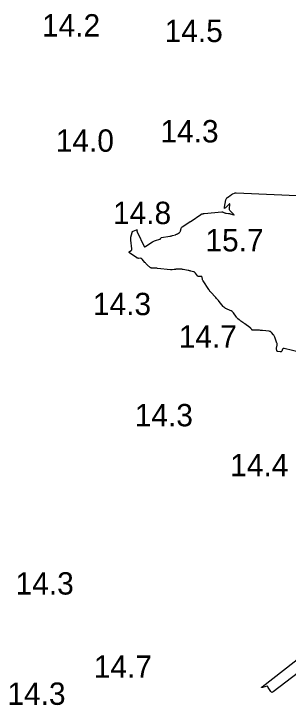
# Model space of a CAD drawing. Extents: x 1023796 to 1112670, y 656573 to 837340.
# Drawn here: x 1101279.7 to 1101341.1, y 687887.6 to 688042.2 of the extents above; entities that cross this region are included whole.
import ezdxf

# ---------------------------------------------------------------- set-up
doc = ezdxf.new("R2010")
doc.units = 0
doc.layers.add('V-CHAN-CONT-15FT', color=7, linetype='Continuous')
doc.layers.add('V-TOPO-SOUN', color=7, linetype='Continuous')

msp = doc.modelspace()

# ---------------------------------------------------------------- linework, layer by layer
at = {"layer": 'V-CHAN-CONT-15FT'}
for points in [[(1101345.78, 687966.02), (1101340.14, 687967.39), (1101340.04, 687967.4), (1101339.95, 687967.38), (1101339.87, 687967.32), (1101339.82, 687967.23), (1101339.62, 687966.81), (1101339.56, 687966.72), (1101339.49, 687966.66), (1101339.4, 687966.63), (1101339.29, 687966.62), (1101338.74, 687966.67), (1101338.65, 687966.69), (1101338.58, 687966.74), (1101338.54, 687966.81), (1101338.52, 687966.9), (1101338.48, 687967.31), (1101338.48, 687967.42), (1101338.48, 687967.52), (1101338.49, 687967.62), (1101338.5, 687967.73), (1101338.58, 687968.15), (1101338.59, 687968.26), (1101338.59, 687968.36), (1101338.57, 687968.47), (1101338.54, 687968.57), (1101338.08, 687969.9), (1101338.02, 687970.04), (1101337.94, 687970.19), (1101337.86, 687970.32), (1101337.76, 687970.45), (1101337.35, 687970.94), (1101337.24, 687971.06), (1101337.11, 687971.14), (1101336.97, 687971.2), (1101336.82, 687971.23), (1101335.35, 687971.39), (1101335.12, 687971.41), (1101334.89, 687971.43), (1101334.65, 687971.44), (1101334.42, 687971.45), (1101333.17, 687971.46), (1101333.1, 687971.47), (1101333.03, 687971.5), (1101332.97, 687971.54), (1101332.92, 687971.59), (1101332.73, 687971.86), (1101332.69, 687971.92), (1101332.63, 687971.98), (1101332.57, 687972.03), (1101332.51, 687972.08), (1101331.39, 687972.86), (1101331.28, 687972.94), (1101331.17, 687973.01), (1101331.06, 687973.09), (1101330.96, 687973.16), (1101330.49, 687973.48), (1101330.4, 687973.54), (1101330.31, 687973.61), (1101330.22, 687973.68), (1101330.14, 687973.75), (1101329.8, 687974.04), (1101329.72, 687974.11), (1101329.65, 687974.19), (1101329.57, 687974.28), (1101329.51, 687974.37), (1101328.83, 687975.32), (1101328.69, 687975.49), (1101328.52, 687975.65), (1101328.34, 687975.77), (1101328.13, 687975.87), (1101327.27, 687976.23), (1101327.06, 687976.33), (1101326.87, 687976.45), (1101326.7, 687976.6), (1101326.55, 687976.77), (1101325.66, 687977.87), (1101325.47, 687978.1), (1101325.27, 687978.32), (1101325.07, 687978.54), (1101324.87, 687978.76), (1101323.68, 687980.03), (1101323.66, 687980.05), (1101323.65, 687980.07), (1101323.64, 687980.09), (1101323.63, 687980.11), (1101323.58, 687980.21), (1101323.57, 687980.22), (1101323.57, 687980.23), (1101323.56, 687980.24), (1101323.55, 687980.25), (1101323.52, 687980.28), (1101323.51, 687980.29), (1101323.5, 687980.3), (1101323.49, 687980.31), (1101323.49, 687980.32), (1101323.38, 687980.48), (1101323.36, 687980.51), (1101323.34, 687980.54), (1101323.32, 687980.56), (1101323.3, 687980.59), (1101322.03, 687982.52), (1101321.98, 687982.61), (1101321.94, 687982.7), (1101321.91, 687982.79), (1101321.9, 687982.88), (1101321.86, 687983.27), (1101321.83, 687983.36), (1101321.79, 687983.42), (1101321.73, 687983.46), (1101321.64, 687983.47), (1101321.16, 687983.47), (1101321.06, 687983.48), (1101320.96, 687983.51), (1101320.88, 687983.56), (1101320.8, 687983.64), (1101320.35, 687984.22), (1101320.25, 687984.33), (1101320.14, 687984.42), (1101320.01, 687984.49), (1101319.87, 687984.54), (1101319.28, 687984.7), (1101319.13, 687984.74), (1101318.98, 687984.78), (1101318.83, 687984.81), (1101318.69, 687984.84), (1101317.62, 687985.05), (1101317.44, 687985.08), (1101317.26, 687985.1), (1101317.07, 687985.11), (1101316.89, 687985.11), (1101315.98, 687985.09), (1101315.88, 687985.08), (1101315.77, 687985.07), (1101315.67, 687985.06), (1101315.56, 687985.05), (1101315.14, 687984.99), (1101315.04, 687984.97), (1101314.93, 687984.97), (1101314.83, 687984.97), (1101314.72, 687984.98), (1101311.86, 687985.3), (1101311.72, 687985.32), (1101311.58, 687985.33), (1101311.44, 687985.34), (1101311.31, 687985.34), (1101310.51, 687985.37), (1101310.49, 687985.37), (1101310.47, 687985.37), (1101310.46, 687985.38), (1101310.44, 687985.38), (1101310.37, 687985.4), (1101310.36, 687985.41), (1101310.34, 687985.41), (1101310.32, 687985.42), (1101310.31, 687985.43), (1101309.52, 687986.12), (1101309.39, 687986.24), (1101309.26, 687986.37), (1101309.14, 687986.5), (1101309.02, 687986.64), (1101308.42, 687987.38), (1101308.34, 687987.46), (1101308.26, 687987.51), (1101308.16, 687987.54), (1101308.05, 687987.55), (1101307.6, 687987.54), (1101307.49, 687987.55), (1101307.39, 687987.57), (1101307.29, 687987.61), (1101307.19, 687987.67), (1101305.58, 687988.8), (1101305.51, 687988.86), (1101305.49, 687988.93), (1101305.51, 687988.99), (1101305.59, 687989.06), (1101305.97, 687989.31), (1101306.05, 687989.38), (1101306.11, 687989.46), (1101306.13, 687989.56), (1101306.13, 687989.67), (1101305.88, 687991.58), (1101305.86, 687991.76), (1101305.86, 687991.94), (1101305.88, 687992.12), (1101305.91, 687992.3), (1101306.15, 687993.34), (1101306.15, 687993.35), (1101306.15, 687993.37), (1101306.15, 687993.38), (1101306.16, 687993.39), (1101306.17, 687993.43), (1101306.18, 687993.44), (1101306.19, 687993.45), (1101306.19, 687993.46), (1101306.2, 687993.47), (1101306.33, 687993.58), (1101306.36, 687993.6), (1101306.38, 687993.62), (1101306.41, 687993.63), (1101306.44, 687993.65), (1101307.18, 687993.93), (1101307.22, 687993.94), (1101307.25, 687993.93), (1101307.27, 687993.91), (1101307.27, 687993.87), (1101307.26, 687993.66), (1101307.26, 687993.61), (1101307.27, 687993.56), (1101307.28, 687993.51), (1101307.3, 687993.46), (1101308.89, 687990.19), (1101308.91, 687990.16), (1101308.94, 687990.15), (1101308.96, 687990.14), (1101309, 687990.14), (1101309.14, 687990.18), (1101309.17, 687990.19), (1101309.21, 687990.2), (1101309.24, 687990.22), (1101309.27, 687990.24), (1101310.74, 687991.22), (1101310.89, 687991.32), (1101311.05, 687991.4), (1101311.21, 687991.47), (1101311.38, 687991.53), (1101312.33, 687991.81), (1101312.37, 687991.83), (1101312.41, 687991.86), (1101312.45, 687991.89), (1101312.48, 687991.92), (1101312.6, 687992.09), (1101312.64, 687992.13), (1101312.67, 687992.16), (1101312.72, 687992.18), (1101312.76, 687992.19), (1101314.62, 687992.5), (1101314.77, 687992.52), (1101314.92, 687992.55), (1101315.07, 687992.59), (1101315.22, 687992.63), (1101315.85, 687992.81), (1101315.97, 687992.86), (1101316.09, 687992.91), (1101316.2, 687992.97), (1101316.31, 687993.04), (1101316.75, 687993.35), (1101316.84, 687993.43), (1101316.92, 687993.52), (1101316.97, 687993.62), (1101317.01, 687993.73), (1101317.12, 687994.21), (1101317.16, 687994.32), (1101317.22, 687994.42), (1101317.29, 687994.51), (1101317.38, 687994.58), (1101319.11, 687995.74), (1101319.13, 687995.76), (1101319.16, 687995.77), (1101319.18, 687995.77), (1101319.2, 687995.78), (1101319.31, 687995.8), (1101319.33, 687995.81), (1101319.35, 687995.82), (1101319.38, 687995.83), (1101319.4, 687995.84), (1101321.54, 687997.36), (1101321.6, 687997.39), (1101321.66, 687997.42), (1101321.72, 687997.45), (1101321.79, 687997.47), (1101322.05, 687997.53), (1101322.11, 687997.54), (1101322.18, 687997.56), (1101322.25, 687997.57), (1101322.31, 687997.57), (1101326.2, 687997.92), (1101326.28, 687997.92), (1101326.37, 687997.91), (1101326.45, 687997.89), (1101326.53, 687997.86), (1101326.85, 687997.72), (1101326.93, 687997.69), (1101327.02, 687997.66), (1101327.1, 687997.64), (1101327.19, 687997.63), (1101327.74, 687997.58), (1101327.85, 687997.56), (1101327.97, 687997.54), (1101328.09, 687997.51), (1101328.2, 687997.48), (1101328.83, 687997.26), (1101328.95, 687997.23), (1101328.99, 687997.24), (1101328.98, 687997.29), (1101328.9, 687997.37), (1101328.16, 687998.1), (1101328.04, 687998.24), (1101327.96, 687998.39), (1101327.92, 687998.57), (1101327.93, 687998.75), (1101328.03, 687999.52), (1101328.04, 687999.67), (1101328, 687999.74), (1101327.93, 687999.72), (1101327.81, 687999.62), (1101327.07, 687998.85), (1101326.92, 687998.73), (1101326.84, 687998.71), (1101326.8, 687998.79), (1101326.82, 687998.98), (1101327.15, 688000.6), (1101327.2, 688000.77), (1101327.27, 688000.91), (1101327.38, 688001.04), (1101327.51, 688001.15), (1101328.3, 688001.72), (1101328.33, 688001.74), (1101328.36, 688001.76), (1101328.39, 688001.79), (1101328.42, 688001.82), (1101328.55, 688001.92), (1101328.58, 688001.94), (1101328.62, 688001.96), (1101328.65, 688001.98), (1101328.69, 688001.99), (1101329.1, 688002.13), (1101329.18, 688002.16), (1101329.26, 688002.17), (1101329.35, 688002.18), (1101329.43, 688002.18), (1101344.74, 688001.54)], [(1101346.21, 687897.03), (1101337.74, 687890.55), (1101337.59, 687890.47), (1101337.45, 687890.46), (1101337.33, 687890.51), (1101337.22, 687890.64), (1101336.62, 687891.56), (1101336.6, 687891.58), (1101336.58, 687891.61), (1101336.56, 687891.64), (1101336.54, 687891.67), (1101336.47, 687891.78), (1101336.45, 687891.8), (1101336.43, 687891.81), (1101336.4, 687891.82), (1101336.37, 687891.81), (1101335.3, 687891.55), (1101335.15, 687891.52), (1101335.09, 687891.54), (1101335.12, 687891.6), (1101335.23, 687891.69), (1101344.81, 687899.18)]]:
    msp.add_lwpolyline(points, dxfattribs=at)

# ---------------------------------------------------------------- texts
at = {"layer": 'V-TOPO-SOUN'}
for s, p in [('14.2 ', (1101286.01, 688037.16)), ('14.5 ', (1101313.44, 688035.92)), ('14.3 ', (1101312.49, 688013.47)), ('14.0 ', (1101289.09, 688011.38)), ('14.8 ', (1101301.89, 687995.2)), ('15.7 ', (1101322.56, 687989.1)), ('14.3 ', (1101297.4, 687974.83)), ('14.7 ', (1101316.59, 687967.54)), ('14.3 ', (1101306.75, 687949.96)), ('14.4 ', (1101328.1, 687938.8)), ('14.3 ', (1101280.11, 687912.33)), ('14.7 ', (1101297.59, 687893.72)), ('14.3 ', (1101278.27, 687887.66))]:
    msp.add_text(s, height=5, dxfattribs=at).set_placement(p)

doc.saveas('drawing.dxf')
